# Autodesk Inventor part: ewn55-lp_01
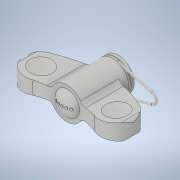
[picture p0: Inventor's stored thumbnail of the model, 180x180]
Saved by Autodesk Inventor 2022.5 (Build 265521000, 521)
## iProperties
Created: 2021-08
Part Number: ewn55-lp_01
Material: 一般
Document SubType Name: Modeling
Designer: ImaoCorp
Density: 1 g/cm^3
Appearance: 既定
Author: ImaoCorp
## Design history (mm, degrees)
feature "ewn55-lp_01"
node "ソリッド1"
